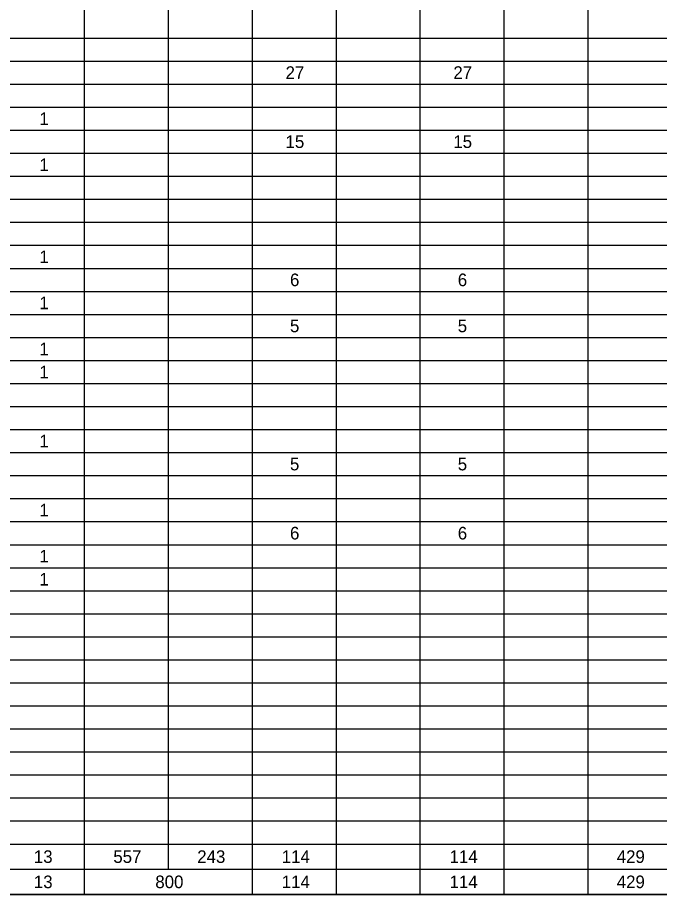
# Model space of a CAD drawing. Extents: x 91011267 to 91022583, y 37007614 to 37014266.
# Drawn here: x 91011661 to 91012044, y 37010175 to 37010699 of the extents above; entities that cross this region are included whole.
import ezdxf

# ---------------------------------------------------------------- set-up
doc = ezdxf.new("R2010")
doc.units = 0
doc.layers.add('SC_Scratch2', color=7, linetype='Continuous')
doc.layers.add('SH_Data', color=7, linetype='Continuous')

msp = doc.modelspace()

# ---------------------------------------------------------------- linework, layer by layer
at = {"layer": 'SC_Scratch2'}
msp.add_lwpolyline([(91011277.35, 37011225.45), (91012802.35, 37011225.45), (91012802.35, 37010175.45), (91011277.35, 37010175.45)], close=True, dxfattribs=at)
at = {"layer": 'SH_Data'}
for p, q in [((91011700.45, 37010851.25), (91011700.45, 37010645.17)), ((91011750.54, 37010851.25), (91011750.54, 37010645.17)), ((91011800.62, 37010851.25), (91011800.62, 37010645.17)), ((91011850.71, 37010851.25), (91011850.71, 37010645.17)), ((91011900.79, 37010851.25), (91011900.79, 37010645.17)), ((91011950.88, 37010851.25), (91011950.88, 37010645.17)), ((91012000.97, 37010851.25), (91012000.97, 37010645.17)), ((91011650.36, 37010686.39), (91011950.88, 37010686.39)), ((91011950.88, 37010686.39), (91012000.97, 37010686.39)), ((91012000.97, 37010686.39), (91012551.92, 37010686.39)), ((91011650.36, 37010672.65), (91011950.88, 37010672.65)), ((91011950.88, 37010672.65), (91012000.97, 37010672.65)), ((91012000.97, 37010672.65), (91012551.92, 37010672.65)), ((91011650.36, 37010658.91), (91011950.88, 37010658.91)), ((91011950.88, 37010658.91), (91012000.97, 37010658.91)), ((91012000.97, 37010658.91), (91012551.92, 37010658.91)), ((91011650.36, 37010645.17), (91011950.88, 37010645.17)), ((91011700.45, 37010645.17), (91011700.45, 37010631.43)), ((91011750.54, 37010645.17), (91011750.54, 37010631.43)), ((91011800.62, 37010645.17), (91011800.62, 37010631.43)), ((91011850.71, 37010645.17), (91011850.71, 37010631.43)), ((91011900.79, 37010645.17), (91011900.79, 37010631.43)), ((91011950.88, 37010645.17), (91012000.97, 37010645.17)), ((91011950.88, 37010645.17), (91011950.88, 37010631.43)), ((91012000.97, 37010645.17), (91012551.92, 37010645.17)), ((91012000.97, 37010645.17), (91012000.97, 37010631.43)), ((91011650.36, 37010631.43), (91011950.88, 37010631.43)), ((91011700.45, 37010631.43), (91011700.45, 37010617.7)), ((91011750.54, 37010631.43), (91011750.54, 37010617.7)), ((91011800.62, 37010631.43), (91011800.62, 37010617.7)), ((91011850.71, 37010631.43), (91011850.71, 37010617.7)), ((91011900.79, 37010631.43), (91011900.79, 37010617.7)), ((91011950.88, 37010631.43), (91012000.97, 37010631.43)), ((91011950.88, 37010631.43), (91011950.88, 37010617.7)), ((91012000.97, 37010631.43), (91012551.92, 37010631.43)), ((91012000.97, 37010631.43), (91012000.97, 37010617.7)), ((91011650.36, 37010617.7), (91011950.88, 37010617.7)), ((91011700.45, 37010617.7), (91011700.45, 37010576.48)), ((91011750.54, 37010617.7), (91011750.54, 37010576.48)), ((91011800.62, 37010617.7), (91011800.62, 37010576.48)), ((91011850.71, 37010617.7), (91011850.71, 37010576.48)), ((91011900.79, 37010617.7), (91011900.79, 37010576.48)), ((91011950.88, 37010617.7), (91012000.97, 37010617.7)), ((91011950.88, 37010617.7), (91011950.88, 37010576.48)), ((91012000.97, 37010617.7), (91012551.92, 37010617.7)), ((91012000.97, 37010617.7), (91012000.97, 37010576.48)), ((91011650.36, 37010603.96), (91011950.88, 37010603.96)), ((91011950.88, 37010603.96), (91012000.97, 37010603.96)), ((91012000.97, 37010603.96), (91012551.92, 37010603.96)), ((91011650.36, 37010590.22), (91011950.88, 37010590.22)), ((91011950.88, 37010590.22), (91012000.97, 37010590.22)), ((91012000.97, 37010590.22), (91012551.92, 37010590.22)), ((91011650.36, 37010576.48), (91011950.88, 37010576.48)), ((91011700.45, 37010576.48), (91011700.45, 37010562.74)), ((91011750.54, 37010576.48), (91011750.54, 37010562.74)), ((91011800.62, 37010576.48), (91011800.62, 37010562.74)), ((91011850.71, 37010576.48), (91011850.71, 37010562.74)), ((91011900.79, 37010576.48), (91011900.79, 37010562.74)), ((91011950.88, 37010576.48), (91012000.97, 37010576.48)), ((91011950.88, 37010576.48), (91011950.88, 37010562.74)), ((91012000.97, 37010576.48), (91012551.92, 37010576.48)), ((91012000.97, 37010576.48), (91012000.97, 37010562.74)), ((91011650.36, 37010562.74), (91011950.88, 37010562.74)), ((91011700.45, 37010562.74), (91011700.45, 37010549)), ((91011750.54, 37010562.74), (91011750.54, 37010549)), ((91011800.62, 37010562.74), (91011800.62, 37010549)), ((91011850.71, 37010562.74), (91011850.71, 37010549)), ((91011900.79, 37010562.74), (91011900.79, 37010549)), ((91011950.88, 37010562.74), (91012000.97, 37010562.74)), ((91011950.88, 37010562.74), (91011950.88, 37010549)), ((91012000.97, 37010562.74), (91012551.92, 37010562.74)), ((91012000.97, 37010562.74), (91012000.97, 37010549)), ((91011650.36, 37010549), (91011950.88, 37010549)), ((91011700.45, 37010549), (91011700.45, 37010507.79)), ((91011750.54, 37010549), (91011750.54, 37010507.79)), ((91011800.62, 37010549), (91011800.62, 37010507.79)), ((91011850.71, 37010549), (91011850.71, 37010507.79)), ((91011900.79, 37010549), (91011900.79, 37010507.79)), ((91011950.88, 37010549), (91012000.97, 37010549)), ((91011950.88, 37010549), (91011950.88, 37010507.79)), ((91012000.97, 37010549), (91012551.92, 37010549)), ((91012000.97, 37010549), (91012000.97, 37010507.79)), ((91011650.36, 37010535.27), (91011950.88, 37010535.27)), ((91011950.88, 37010535.27), (91012000.97, 37010535.27)), ((91012000.97, 37010535.27), (91012551.92, 37010535.27)), ((91011650.36, 37010521.53), (91011950.88, 37010521.53)), ((91011950.88, 37010521.53), (91012000.97, 37010521.53)), ((91012000.97, 37010521.53), (91012551.92, 37010521.53)), ((91011650.36, 37010507.79), (91011950.88, 37010507.79)), ((91011700.45, 37010507.79), (91011700.45, 37010494.05)), ((91011750.54, 37010507.79), (91011750.54, 37010494.05)), ((91011800.62, 37010507.79), (91011800.62, 37010494.05)), ((91011850.71, 37010507.79), (91011850.71, 37010494.05)), ((91011900.79, 37010507.79), (91011900.79, 37010494.05)), ((91011950.88, 37010507.79), (91012000.97, 37010507.79)), ((91011950.88, 37010507.79), (91011950.88, 37010494.05)), ((91012000.97, 37010507.79), (91012551.92, 37010507.79)), ((91012000.97, 37010507.79), (91012000.97, 37010494.05)), ((91011650.36, 37010494.05), (91011950.88, 37010494.05)), ((91011700.45, 37010494.05), (91011700.45, 37010480.31)), ((91011750.54, 37010494.05), (91011750.54, 37010480.31)), ((91011800.62, 37010494.05), (91011800.62, 37010480.31)), ((91011850.71, 37010494.05), (91011850.71, 37010480.31)), ((91011900.79, 37010494.05), (91011900.79, 37010480.31)), ((91011950.88, 37010494.05), (91012000.97, 37010494.05)), ((91011950.88, 37010494.05), (91011950.88, 37010480.31)), ((91012000.97, 37010494.05), (91012551.92, 37010494.05)), ((91012000.97, 37010494.05), (91012000.97, 37010480.31)), ((91011650.36, 37010480.31), (91011950.88, 37010480.31)), ((91011700.45, 37010480.31), (91011700.45, 37010175.45)), ((91011750.54, 37010480.31), (91011750.54, 37010190.5)), ((91011800.62, 37010480.31), (91011800.62, 37010175.45)), ((91011850.71, 37010480.31), (91011850.71, 37010175.45)), ((91011900.79, 37010480.31), (91011900.79, 37010175.45)), ((91011950.88, 37010480.31), (91012000.97, 37010480.31)), ((91011950.88, 37010480.31), (91011950.88, 37010175.45)), ((91012000.97, 37010480.31), (91012551.92, 37010480.31)), ((91012000.97, 37010480.31), (91012000.97, 37010175.45)), ((91011650.36, 37010466.57), (91011950.88, 37010466.57)), ((91011950.88, 37010466.57), (91012000.97, 37010466.57)), ((91012000.97, 37010466.57), (91012551.92, 37010466.57)), ((91011650.36, 37010452.84), (91011950.88, 37010452.84)), ((91011950.88, 37010452.84), (91012000.97, 37010452.84)), ((91012000.97, 37010452.84), (91012551.92, 37010452.84)), ((91011650.36, 37010439.1), (91011950.88, 37010439.1)), ((91011950.88, 37010439.1), (91012000.97, 37010439.1)), ((91012000.97, 37010439.1), (91012551.92, 37010439.1)), ((91011650.36, 37010425.36), (91011950.88, 37010425.36)), ((91011950.88, 37010425.36), (91012000.97, 37010425.36)), ((91012000.97, 37010425.36), (91012551.92, 37010425.36)), ((91011650.36, 37010411.62), (91011950.88, 37010411.62)), ((91011950.88, 37010411.62), (91012000.97, 37010411.62)), ((91012000.97, 37010411.62), (91012551.92, 37010411.62)), ((91011650.36, 37010397.88), (91011950.88, 37010397.88)), ((91011950.88, 37010397.88), (91012000.97, 37010397.88)), ((91012000.97, 37010397.88), (91012551.92, 37010397.88)), ((91011650.36, 37010384.14), (91011950.88, 37010384.14)), ((91011950.88, 37010384.14), (91012000.97, 37010384.14)), ((91012000.97, 37010384.14), (91012551.92, 37010384.14)), ((91011650.36, 37010370.41), (91011950.88, 37010370.41)), ((91011950.88, 37010370.41), (91012000.97, 37010370.41)), ((91012000.97, 37010370.41), (91012551.92, 37010370.41)), ((91011650.36, 37010356.67), (91011950.88, 37010356.67)), ((91011950.88, 37010356.67), (91012000.97, 37010356.67)), ((91012000.97, 37010356.67), (91012551.92, 37010356.67)), ((91011650.36, 37010342.93), (91011950.88, 37010342.93)), ((91011950.88, 37010342.93), (91012000.97, 37010342.93)), ((91012000.97, 37010342.93), (91012551.92, 37010342.93)), ((91011650.36, 37010329.19), (91011950.88, 37010329.19)), ((91011950.88, 37010329.19), (91012000.97, 37010329.19)), ((91012000.97, 37010329.19), (91012551.92, 37010329.19)), ((91011650.36, 37010315.45), (91011950.88, 37010315.45)), ((91011950.88, 37010315.45), (91012000.97, 37010315.45)), ((91012000.97, 37010315.45), (91012551.92, 37010315.45)), ((91011650.36, 37010301.71), (91011950.88, 37010301.71)), ((91011950.88, 37010301.71), (91012000.97, 37010301.71)), ((91012000.97, 37010301.71), (91012551.92, 37010301.71)), ((91011650.36, 37010287.98), (91011950.88, 37010287.98)), ((91011950.88, 37010287.98), (91012000.97, 37010287.98)), ((91012000.97, 37010287.98), (91012551.92, 37010287.98)), ((91011650.36, 37010274.24), (91011950.88, 37010274.24)), ((91011950.88, 37010274.24), (91012000.97, 37010274.24)), ((91012000.97, 37010274.24), (91012551.92, 37010274.24)), ((91011650.36, 37010260.5), (91011950.88, 37010260.5)), ((91011950.88, 37010260.5), (91012000.97, 37010260.5)), ((91012000.97, 37010260.5), (91012551.92, 37010260.5)), ((91011650.36, 37010246.76), (91011950.88, 37010246.76)), ((91011950.88, 37010246.76), (91012000.97, 37010246.76)), ((91012000.97, 37010246.76), (91012551.92, 37010246.76)), ((91011650.36, 37010233.02), (91011950.88, 37010233.02)), ((91011950.88, 37010233.02), (91012000.97, 37010233.02)), ((91012000.97, 37010233.02), (91012551.92, 37010233.02)), ((91011650.36, 37010219.29), (91011950.88, 37010219.29)), ((91011950.88, 37010219.29), (91012000.97, 37010219.29)), ((91012000.97, 37010219.29), (91012551.92, 37010219.29)), ((91011650.36, 37010205.55), (91011950.88, 37010205.55)), ((91011950.88, 37010205.55), (91012000.97, 37010205.55)), ((91012000.97, 37010205.55), (91012551.92, 37010205.55)), ((91011650.36, 37010190.5), (91011950.88, 37010190.5)), ((91011950.88, 37010190.5), (91012000.97, 37010190.5)), ((91012000.97, 37010190.5), (91012551.92, 37010190.5)), ((91011650.36, 37010175.45), (91011950.88, 37010175.45)), ((91011950.88, 37010175.45), (91012000.97, 37010175.45)), ((91012000.97, 37010175.45), (91012551.92, 37010175.45))]:
    msp.add_line(p, q, dxfattribs=at)

# ---------------------------------------------------------------- texts
for s, height, p in [('27', 7.523, (91011820.58, 37010662.02)), ('27', 7.523, (91011920.76, 37010662.02)), ('1', 7.52, (91011673.63, 37010634.54)), ('15', 7.523, (91011820.56, 37010620.8)), ('15', 7.523, (91011920.73, 37010620.8)), ('1', 7.52, (91011673.63, 37010607.07)), ('1', 7.52, (91011673.63, 37010552.11)), ('6', 7.52, (91011823.23, 37010538.37)), ('6', 7.52, (91011923.4, 37010538.37)), ('1', 7.52, (91011673.63, 37010524.64)), ('5', 7.52, (91011823.21, 37010510.9)), ('5', 7.52, (91011923.38, 37010510.9)), ('1', 7.52, (91011673.63, 37010497.16)), ('1', 7.52, (91011673.63, 37010483.42)), ('1', 7.52, (91011673.63, 37010442.21)), ('5', 7.52, (91011823.21, 37010428.47)), ('5', 7.52, (91011923.38, 37010428.47)), ('1', 7.52, (91011673.63, 37010400.99)), ('6', 7.52, (91011823.23, 37010387.25)), ('6', 7.52, (91011923.4, 37010387.25)), ('1', 7.52, (91011673.63, 37010373.51)), ('1', 7.52, (91011673.63, 37010359.78)), ('13', 7.523, (91011670.32, 37010194.26)), ('557', 7.523, (91011717.76, 37010194.26)), ('243', 7.523, (91011767.85, 37010194.26)), ('114', 7.523, (91011818.3, 37010194.26)), ('114', 7.523, (91011918.48, 37010194.26)), ('429', 7.523, (91012018.27, 37010194.26)), ('13', 7.523, (91011670.32, 37010179.21)), ('800', 7.523, (91011742.82, 37010179.21)), ('114', 7.523, (91011818.3, 37010179.21)), ('114', 7.523, (91011918.48, 37010179.21)), ('429', 7.523, (91012018.27, 37010179.21))]:
    msp.add_text(s, height=height, dxfattribs=at).set_placement(p)

doc.saveas('drawing.dxf')
